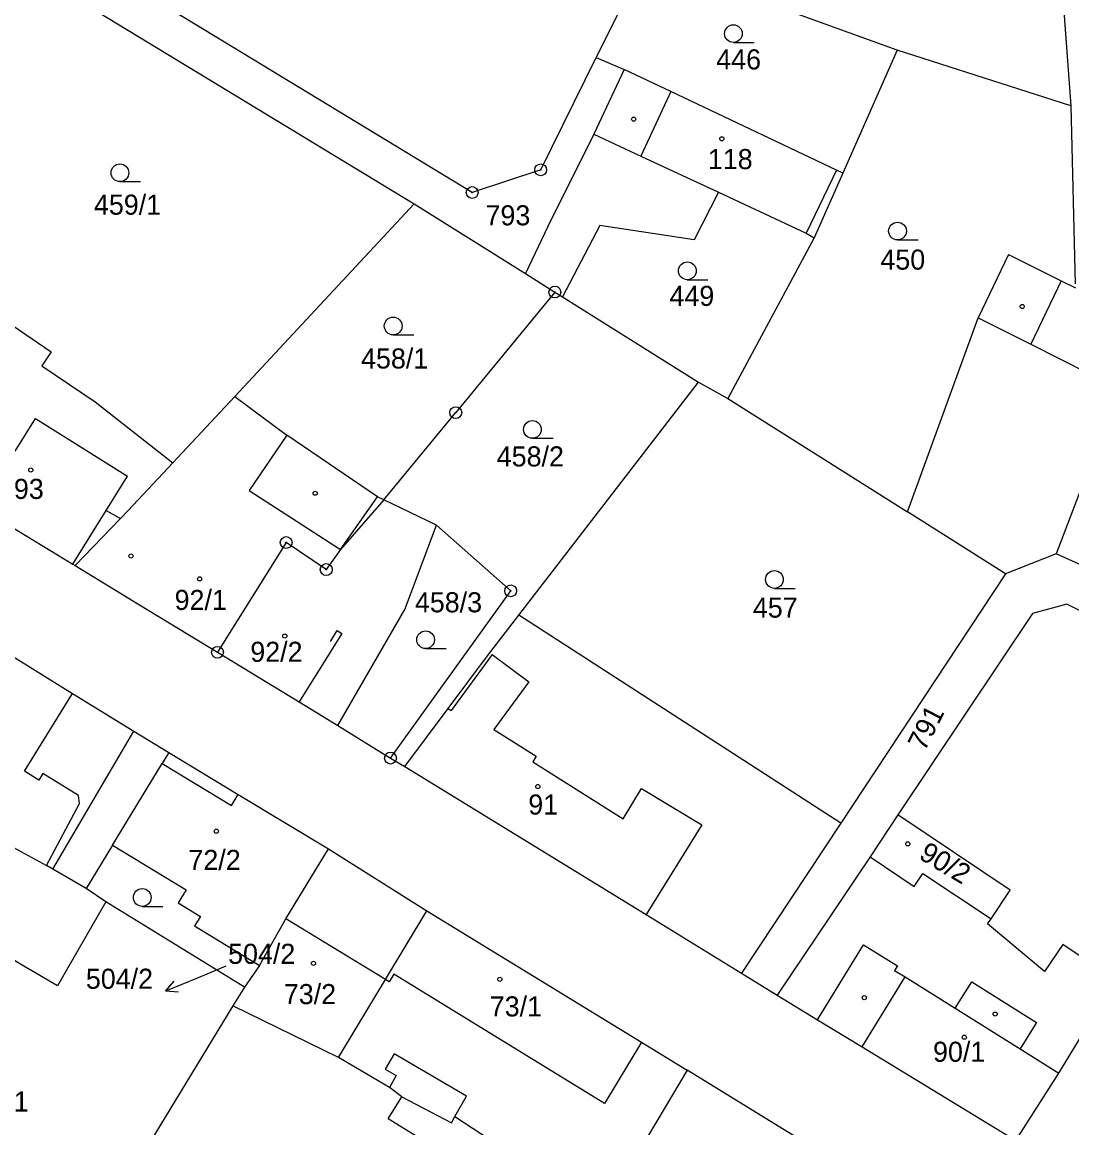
# Model space of a CAD drawing. Extents: x -735249 to -729401, y -1124843 to -1121828.
# Drawn here: x -734626.3 to -734537.4, y -1122809.7 to -1122716.1 of the extents above; entities that cross this region are included whole.
import ezdxf

# ---------------------------------------------------------------- set-up
doc = ezdxf.new("R2010")
doc.units = 0
for name, color, linetype in [('Vrstva 1', 7, 'Continuous'), ('Vrstva 16', 7, 'Continuous'), ('Vrstva 18', 7, 'Continuous'), ('Vrstva 19', 7, 'Continuous'), ('Vrstva 25', 7, 'Continuous'), ('Vrstva 4', 7, 'Continuous')]:
    doc.layers.add(name, color=color, linetype=linetype)

msp = doc.modelspace()

# ---------------------------------------------------------------- linework, layer by layer
at = {"layer": 'Vrstva 1'}
for points in [[(-734588.15, -1122730.56), (-734619.81, -1122711.3)], [(-734573.51, -1122710.77), (-734577.64, -1122719.13)], [(-734552.15, -1122718.52), (-734573.51, -1122710.77)], [(-734538.24, -1122712.53), (-734537.44, -1122723.23)], [(-734621.48, -1122714.29), (-734593.05, -1122731.53)], [(-734552.15, -1122718.52), (-734556.75, -1122728.92)], [(-734537.44, -1122723.23), (-734552.15, -1122718.52)], [(-734582.35, -1122728.64), (-734577.64, -1122719.13)], [(-734577.64, -1122719.13), (-734575.29, -1122720.15)], [(-734575.29, -1122720.15), (-734577.84, -1122725.63)], [(-734571.33, -1122722.02), (-734575.29, -1122720.15)], [(-734557.29, -1122728.66), (-734571.33, -1122722.02)], [(-734537.44, -1122723.23), (-734537.08, -1122738.3)], [(-734577.84, -1122725.63), (-734580.93, -1122731.8)], [(-734582.35, -1122728.64), (-734588.15, -1122730.56)], [(-734556.75, -1122728.92), (-734559.18, -1122734.41)], [(-734556.75, -1122728.92), (-734557.29, -1122728.66)], [(-734567.29, -1122730.54), (-734569.36, -1122734.58)], [(-734567.29, -1122730.54), (-734559.86, -1122734)], [(-734593.05, -1122731.53), (-734608.26, -1122747.82)], [(-734593.05, -1122731.53), (-734583.63, -1122737.43)], [(-734580.93, -1122731.8), (-734581.45, -1122732.85)], [(-734581.45, -1122732.85), (-734583.63, -1122737.43)], [(-734577.34, -1122733.34), (-734580.5, -1122739.39)], [(-734569.36, -1122734.58), (-734577.34, -1122733.34)], [(-734559.86, -1122734), (-734559.18, -1122734.41)], [(-734559.18, -1122734.41), (-734566.5, -1122747.99)], [(-734542.73, -1122735.82), (-734545.3, -1122741.16)], [(-734542.73, -1122735.82), (-734538.26, -1122738.04)], [(-734633.5, -1122737.45), (-734623.8, -1122744.04)], [(-734583.63, -1122737.43), (-734581.15, -1122738.99)], [(-734538.26, -1122738.04), (-734537.07, -1122738.63)], [(-734581.15, -1122738.99), (-734589.54, -1122749.19)], [(-734581.15, -1122738.99), (-734580.5, -1122739.39)], [(-734580.5, -1122739.39), (-734568.97, -1122746.61)], [(-734551.28, -1122757.6), (-734545.3, -1122741.16)], [(-734623.8, -1122744.04), (-734624.6, -1122745.23)], [(-734624.6, -1122745.23), (-734620.08, -1122748.29)], [(-734584.21, -1122766.35), (-734568.97, -1122746.61)], [(-734568.97, -1122746.61), (-734566.5, -1122747.99)], [(-734613.51, -1122753.44), (-734608.26, -1122747.82)], [(-734608.26, -1122747.82), (-734603.85, -1122751.1)], [(-734566.5, -1122747.99), (-734551.28, -1122757.6)], [(-734533.37, -1122747.19), (-734538.69, -1122761.14)], [(-734620.08, -1122748.29), (-734613.51, -1122753.44)], [(-734595.64, -1122756.58), (-734589.54, -1122749.19)], [(-734596.17, -1122756.33), (-734603.85, -1122751.1)], [(-734617.27, -1122757.47), (-734613.51, -1122753.44)], [(-734635.64, -1122753.72), (-734621.98, -1122762.01)], [(-734595.64, -1122756.58), (-734596.17, -1122756.33)], [(-734595.64, -1122756.58), (-734599.31, -1122760.77)], [(-734591.17, -1122758.71), (-734595.64, -1122756.58)], [(-734621.98, -1122762.01), (-734619.15, -1122757.49)], [(-734619.15, -1122757.49), (-734617.94, -1122758.17)], [(-734617.94, -1122758.17), (-734617.27, -1122757.47)], [(-734542.98, -1122762.85), (-734551.28, -1122757.6)], [(-734593.86, -1122765.86), (-734591.17, -1122758.71)], [(-734584.89, -1122764.28), (-734591.17, -1122758.71)], [(-734603.9, -1122760.19), (-734606.64, -1122764.57)], [(-734600.51, -1122762.48), (-734603.9, -1122760.19)], [(-734599.31, -1122760.77), (-734600.51, -1122762.48)], [(-734538.69, -1122761.14), (-734542.98, -1122762.85)], [(-734528.92, -1122765.53), (-734538.69, -1122761.14)], [(-734621.98, -1122762.01), (-734621.77, -1122762.14)], [(-734621.77, -1122762.14), (-734616.33, -1122765.46)], [(-734542.98, -1122762.85), (-734556.94, -1122783.95)], [(-734606.64, -1122764.57), (-734609.72, -1122769.48)], [(-734595.07, -1122778.44), (-734584.89, -1122764.28)], [(-734616.33, -1122765.46), (-734609.72, -1122769.48)], [(-734537.79, -1122765.42), (-734540.69, -1122766.2)], [(-734530.7, -1122768.99), (-734537.79, -1122765.42)], [(-734599.53, -1122775.69), (-734593.86, -1122765.86)], [(-734586.86, -1122769.78), (-734584.21, -1122766.35)], [(-734556.94, -1122783.95), (-734584.21, -1122766.35)], [(-734540.69, -1122766.2), (-734552.09, -1122783.25)], [(-734627.91, -1122769.31), (-734622, -1122772.96)], [(-734609.72, -1122769.48), (-734602.81, -1122773.69)], [(-734590.18, -1122774.24), (-734586.86, -1122769.78)], [(-734622, -1122772.96), (-734616.8, -1122776.17)], [(-734602.81, -1122773.69), (-734599.53, -1122775.69)], [(-734593.85, -1122779.15), (-734590.18, -1122774.24)], [(-734599.53, -1122775.69), (-734595.07, -1122778.44)], [(-734623.67, -1122787.83), (-734616.8, -1122776.17)], [(-734616.8, -1122776.17), (-734613.83, -1122777.98)], [(-734613.83, -1122777.98), (-734607.96, -1122781.52)], [(-734595.07, -1122778.44), (-734593.85, -1122779.15)], [(-734593.85, -1122779.15), (-734573.42, -1122791.69)], [(-734607.96, -1122781.52), (-734600.31, -1122786.13)], [(-734552.09, -1122783.25), (-734554.46, -1122786.79)], [(-734542.58, -1122789.61), (-734552.09, -1122783.25)], [(-734556.94, -1122783.95), (-734565.35, -1122796.65)], [(-734627.62, -1122785.66), (-734624.2, -1122787.53)], [(-734618.6, -1122785.8), (-734620.83, -1122789.47)], [(-734618.6, -1122785.8), (-734612.38, -1122789.59)], [(-734603.93, -1122792.05), (-734600.31, -1122786.13)], [(-734600.31, -1122786.13), (-734592, -1122791.37)], [(-734554.46, -1122786.79), (-734562.31, -1122798.52)], [(-734554.46, -1122786.79), (-734550.72, -1122789.3)], [(-734623.67, -1122787.83), (-734624.2, -1122787.53)], [(-734620.83, -1122789.47), (-734623.67, -1122787.83)], [(-734550.72, -1122789.3), (-734549.98, -1122788.2)], [(-734549.98, -1122788.2), (-734544.21, -1122792.05)], [(-734619.17, -1122790.6), (-734620.83, -1122789.47)], [(-734612.38, -1122789.59), (-734613.05, -1122790.7)], [(-734544.21, -1122792.05), (-734542.58, -1122789.61)], [(-734619.17, -1122790.6), (-734623.26, -1122797.73)], [(-734607.44, -1122797.84), (-734619.17, -1122790.6)], [(-734613.05, -1122790.7), (-734611.17, -1122791.84)], [(-734611.17, -1122791.84), (-734611.67, -1122792.65)], [(-734595.5, -1122797.18), (-734592, -1122791.37)], [(-734592, -1122791.37), (-734573.8, -1122802.48)], [(-734573.42, -1122791.69), (-734565.35, -1122796.65)], [(-734611.67, -1122792.65), (-734606.17, -1122796)], [(-734606.17, -1122796), (-734603.93, -1122792.05)], [(-734544.5, -1122792.48), (-734544.21, -1122792.05)], [(-734539.67, -1122796.51), (-734544.5, -1122792.48)], [(-734626.11, -1122796.06), (-734629.93, -1122793.76)], [(-734538.14, -1122794.21), (-734539.67, -1122796.51)], [(-734535.06, -1122796.27), (-734538.14, -1122794.21)], [(-734623.26, -1122797.73), (-734626.11, -1122796.06)], [(-734606.17, -1122796), (-734607.44, -1122797.84)], [(-734565.35, -1122796.65), (-734562.31, -1122798.52)], [(-734599.47, -1122803.78), (-734595.5, -1122797.18)], [(-734607.44, -1122797.84), (-734608.41, -1122799.41)], [(-734562.31, -1122798.52), (-734558.92, -1122800.59)], [(-734608.41, -1122799.41), (-734623.86, -1122824.8)], [(-734599.47, -1122803.78), (-734608.41, -1122799.41)], [(-734538.46, -1122805.1), (-734535.06, -1122799.51)], [(-734558.92, -1122800.59), (-734555.13, -1122802.89)], [(-734573.8, -1122802.48), (-734569.95, -1122804.85)], [(-734555.13, -1122802.89), (-734542.12, -1122810.82)], [(-734595.15, -1122806.33), (-734599.47, -1122803.78)], [(-734569.95, -1122804.85), (-734573.21, -1122810.37)], [(-734558.43, -1122811.93), (-734569.95, -1122804.85)], [(-734542.12, -1122810.82), (-734538.46, -1122805.1)], [(-734594.11, -1122807.13), (-734595.15, -1122806.33)], [(-734595.27, -1122808.99), (-734594.11, -1122807.13)], [(-734594.11, -1122807.13), (-734589.91, -1122809.33)], [(-734589.91, -1122809.33), (-734589.61, -1122808.79)], [(-734589.61, -1122808.79), (-734577.12, -1122816.97)], [(-734584.99, -1122815.34), (-734595.27, -1122808.99)]]:
    msp.add_lwpolyline(points, dxfattribs=at)
at = {"layer": 'Vrstva 16'}
msp.add_lwpolyline([(-734609.02, -1122796.06), (-734611.36, -1122797.03)], dxfattribs=at)
at = {"layer": 'Vrstva 25'}
for points in [[(-734566.03, -1122717.86), (-734564.28, -1122717.86)], [(-734617.98, -1122729.64), (-734616.23, -1122729.64)], [(-734552.13, -1122734.57), (-734550.38, -1122734.57)], [(-734569.93, -1122737.94), (-734568.18, -1122737.94)], [(-734594.84, -1122742.61), (-734593.09, -1122742.61)], [(-734583.05, -1122751.37), (-734581.3, -1122751.37)], [(-734562.55, -1122764.07), (-734560.8, -1122764.07)], [(-734592.09, -1122769.17), (-734590.34, -1122769.17)], [(-734616.09, -1122790.99), (-734614.34, -1122790.99)], [(-734611.36, -1122797.03), (-734614.133, -1122798.173)], [(-734613.018, -1122798.254), (-734614.133, -1122798.173), (-734613.399, -1122797.329)]]:
    msp.add_lwpolyline(points, dxfattribs=at)
for centre, radius in [((-734566.03, -1122717.11), 0.75), ((-734574.47, -1122724.35), 0.175), ((-734567.01, -1122726.01), 0.175), ((-734617.98, -1122728.89), 0.75), ((-734582.35, -1122728.64), 0.5), ((-734582.35, -1122728.64), 0.032), ((-734588.15, -1122730.56), 0.5), ((-734588.15, -1122730.56), 0.032), ((-734552.13, -1122733.82), 0.75), ((-734569.93, -1122737.19), 0.75), ((-734581.15, -1122738.99), 0.5), ((-734581.15, -1122738.99), 0.032), ((-734541.57, -1122740.21), 0.175), ((-734594.84, -1122741.86), 0.75), ((-734589.54, -1122749.19), 0.5), ((-734589.54, -1122749.19), 0.032), ((-734583.05, -1122750.62), 0.75), ((-734625.53, -1122754.05), 0.175), ((-734601.45, -1122756.02), 0.175), ((-734603.9, -1122760.19), 0.5), ((-734603.9, -1122760.19), 0.032), ((-734617.05, -1122761.33), 0.175), ((-734600.51, -1122762.48), 0.5), ((-734600.51, -1122762.48), 0.032), ((-734562.55, -1122763.32), 0.75), ((-734611.23, -1122763.27), 0.175), ((-734584.89, -1122764.28), 0.5), ((-734584.89, -1122764.28), 0.032), ((-734592.09, -1122768.42), 0.75), ((-734604.02, -1122768.11), 0.175), ((-734609.72, -1122769.48), 0.5), ((-734609.72, -1122769.48), 0.032), ((-734595.07, -1122778.44), 0.5), ((-734595.07, -1122778.44), 0.032), ((-734582.59, -1122780.85), 0.175), ((-734609.82, -1122784.63), 0.175), ((-734551.26, -1122785.7), 0.175), ((-734616.09, -1122790.24), 0.75), ((-734601.59, -1122795.81), 0.175), ((-734585.81, -1122797.17), 0.175), ((-734554.94, -1122798.72), 0.175), ((-734543.86, -1122800.11), 0.175), ((-734546.47, -1122802.07), 0.175)]:
    msp.add_circle(centre, radius, dxfattribs=at)
at = {"layer": 'Vrstva 4'}
for points in [[(-734571.33, -1122722.02), (-734573.88, -1122727.47)], [(-734577.84, -1122725.63), (-734573.88, -1122727.47)], [(-734573.88, -1122727.47), (-734567.29, -1122730.54)], [(-734557.29, -1122728.66), (-734559.86, -1122734)], [(-734538.26, -1122738.04), (-734540.85, -1122743.41)], [(-734545.3, -1122741.16), (-734540.85, -1122743.41)], [(-734540.85, -1122743.41), (-734533.37, -1122747.19)], [(-734626.86, -1122752.46), (-734625.12, -1122749.7)], [(-734625.12, -1122749.7), (-734617.33, -1122754.57)], [(-734603.85, -1122751.1), (-734607.04, -1122755.79)], [(-734619.15, -1122757.49), (-734617.33, -1122754.57)], [(-734607.04, -1122755.79), (-734599.31, -1122760.77)], [(-734599.31, -1122760.77), (-734596.17, -1122756.33)], [(-734621.77, -1122762.14), (-734617.94, -1122758.17)], [(-734600.15, -1122768.56), (-734599.57, -1122767.64)], [(-734599.57, -1122767.64), (-734599.19, -1122767.88)], [(-734599.19, -1122767.88), (-734602.81, -1122773.69)], [(-734586.47, -1122769.68), (-734589.93, -1122774.42)], [(-734586.47, -1122769.68), (-734583.34, -1122771.97)], [(-734583.34, -1122771.97), (-734586.31, -1122776.02)], [(-734626.06, -1122779.56), (-734622, -1122772.96)], [(-734590.18, -1122774.24), (-734589.93, -1122774.42)], [(-734586.31, -1122776.02), (-734582.72, -1122778.29)], [(-734613.83, -1122777.98), (-734614.39, -1122778.91)], [(-734618.6, -1122785.8), (-734614.39, -1122778.91)], [(-734614.39, -1122778.91), (-734608.52, -1122782.45)], [(-734582.72, -1122778.29), (-734583.01, -1122778.75)], [(-734583.01, -1122778.75), (-734575.36, -1122783.59)], [(-734624.86, -1122780.3), (-734626.06, -1122779.56)], [(-734624.52, -1122779.75), (-734624.86, -1122780.3)], [(-734621.48, -1122781.62), (-734624.52, -1122779.75)], [(-734621.41, -1122782.28), (-734621.48, -1122781.62)], [(-734608.52, -1122782.45), (-734607.96, -1122781.52)], [(-734575.36, -1122783.59), (-734573.81, -1122781.02)], [(-734573.81, -1122781.02), (-734568.7, -1122784.1)], [(-734624.2, -1122787.53), (-734621.41, -1122782.28)], [(-734568.7, -1122784.1), (-734573.42, -1122791.69)], [(-734595.5, -1122797.18), (-734603.93, -1122792.05)], [(-734558.92, -1122800.59), (-734555.01, -1122794.24)], [(-734555.01, -1122794.24), (-734552.14, -1122796.03)], [(-734552.14, -1122796.03), (-734552.38, -1122796.41)], [(-734552.38, -1122796.41), (-734551.48, -1122796.97)], [(-734595.18, -1122797.38), (-734595.5, -1122797.18)], [(-734594.79, -1122796.74), (-734595.18, -1122797.38)], [(-734576.95, -1122807.69), (-734594.79, -1122796.74)], [(-734555.13, -1122802.89), (-734551.48, -1122796.97)], [(-734551.48, -1122796.97), (-734547.24, -1122799.62)], [(-734547.24, -1122799.62), (-734545.83, -1122797.37)], [(-734545.83, -1122797.37), (-734540.35, -1122800.82)], [(-734547.24, -1122799.62), (-734541.74, -1122803.05)], [(-734540.35, -1122800.82), (-734541.74, -1122803.05)], [(-734573.8, -1122802.48), (-734576.95, -1122807.69)], [(-734541.74, -1122803.05), (-734538.46, -1122805.1)], [(-734594.75, -1122803.47), (-734595.52, -1122804.78)], [(-734588.64, -1122807.07), (-734594.75, -1122803.47)], [(-734595.52, -1122804.78), (-734594.58, -1122805.3)], [(-734594.58, -1122805.3), (-734595.15, -1122806.33)], [(-734589.61, -1122808.79), (-734588.64, -1122807.07)]]:
    msp.add_lwpolyline(points, dxfattribs=at)

# ---------------------------------------------------------------- texts
at = {"layer": 'Vrstva 16'}
msp.add_text('504/2', height=1.7, dxfattribs=at).set_placement((-734620.866, -1122797.97))
at = {"layer": 'Vrstva 18'}
for s, p in [('446', (-734567.48, -1122720.14)), ('459/1', (-734620.18, -1122732.44)), ('793', (-734587.02, -1122733.34)), ('450', (-734553.58, -1122737.09)), ('449', (-734571.44, -1122740.16)), ('458/1', (-734597.56, -1122745.46)), ('458/2', (-734586.07, -1122753.75)), ('458/3', (-734593, -1122766.1)), ('457', (-734564.38, -1122766.55)), ('504/2', (-734608.82, -1122795.86)), ('504/1', (-734631.4, -1122808.36))]:
    msp.add_text(s, height=1.7, dxfattribs=at).set_placement(p)
msp.add_text('791', height=1.7, rotation=63.1005, dxfattribs=at).set_placement((-734549.827, -1122777.932))
at = {"layer": 'Vrstva 19'}
for s, p in [('118', (-734568.19, -1122728.58)), ('93', (-734626.96, -1122756.5)), ('92/1', (-734613.35, -1122765.9)), ('92/2', (-734606.94, -1122770.29)), ('91', (-734583.4, -1122783.22)), ('72/2', (-734612.18, -1122787.91)), ('73/2', (-734604.1, -1122799.27)), ('73/1', (-734586.66, -1122800.31)), ('90/1', (-734549.12, -1122804.15))]:
    msp.add_text(s, height=1.7, dxfattribs=at).set_placement(p)
msp.add_text('90/2', height=1.7, rotation=329.10262, dxfattribs=at).set_placement((-734550.416, -1122786.902))

doc.saveas('drawing.dxf')
